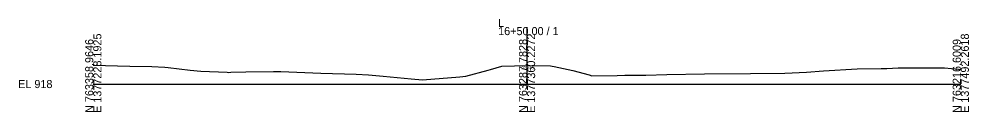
# Model space of a CAD drawing. Extents: x -26 to 303, y -10 to 6523.
# Drawn here: x -25.7 to 302.8, y 6490.3 to 6522.5 of the extents above; entities that cross this region are included whole.
import ezdxf

# ---------------------------------------------------------------- set-up
doc = ezdxf.new("R2010")
doc.units = 0
for name, color, linetype in [('Exist Cross Section Cell', 7, 'Continuous'), ('Exist XS Center Line Elevation Label', 7, 'Continuous'), ('Exist XS Ground Line', 7, 'Continuous')]:
    doc.layers.add(name, color=color, linetype=linetype)

msp = doc.modelspace()

# ---------------------------------------------------------------- linework, layer by layer
at = {"layer": 'Exist Cross Section Cell'}
for p, q in [((150, 6500), (150, 6519.73)), ((0, 6500), (150, 6500)), ((150, 6500), (300, 6500))]:
    msp.add_line(p, q, dxfattribs=at)
at = {"layer": 'Exist XS Ground Line'}
for p, q in [((0, 6506.58), (12.58, 6506.17)), ((12.58, 6506.17), (20.24, 6506.09)), ((20.24, 6506.09), (24.73, 6505.83)), ((24.73, 6505.83), (25.88, 6505.69)), ((25.88, 6505.69), (33.52, 6504.75)), ((136.51, 6504.81), (137.33, 6505)), ((137.33, 6505), (141.25, 6506.22)), ((141.25, 6506.22), (150.01, 6506.4)), ((150.01, 6506.4), (158.1, 6506.25)), ((158.1, 6506.25), (158.65, 6506.24)), ((158.65, 6506.24), (159.41, 6506.08)), ((159.41, 6506.08), (165.89, 6504.71)), ((254.47, 6504.72), (262.17, 6505.14)), ((262.17, 6505.14), (264.11, 6505.21)), ((264.11, 6505.21), (272.51, 6505.33)), ((272.51, 6505.33), (274.38, 6505.42)), ((274.38, 6505.42), (278.3, 6505.63)), ((278.3, 6505.63), (283.94, 6505.59)), ((283.94, 6505.59), (288.94, 6505.61)), ((288.94, 6505.61), (294.35, 6505.57)), ((294.35, 6505.57), (299.25, 6505.1)), ((299.25, 6505.1), (300, 6505.04)), ((33.52, 6504.75), (37.18, 6504.45)), ((37.18, 6504.45), (46.24, 6504.1)), ((46.24, 6504.1), (46.74, 6504.05)), ((46.74, 6504.05), (47.54, 6504.11)), ((47.54, 6504.11), (52.77, 6504.19)), ((52.77, 6504.19), (62.28, 6504.32)), ((62.28, 6504.32), (63.47, 6504.33)), ((63.47, 6504.33), (64.9, 6504.32)), ((64.9, 6504.32), (78.72, 6503.77)), ((78.72, 6503.77), (90.94, 6503.38)), ((90.94, 6503.38), (95.22, 6503.21)), ((95.22, 6503.21), (100.29, 6502.72)), ((100.29, 6502.72), (109.9, 6501.82)), ((109.9, 6501.82), (113.86, 6501.43)), ((113.86, 6501.43), (126.79, 6502.46)), ((126.79, 6502.46), (128.89, 6502.76)), ((128.89, 6502.76), (136.51, 6504.81)), ((165.89, 6504.71), (171.5, 6503.13)), ((171.5, 6503.13), (172.43, 6502.88)), ((172.43, 6502.88), (181.2, 6502.94)), ((181.2, 6502.94), (183.81, 6503.06)), ((183.81, 6503.06), (187.89, 6503.04)), ((187.89, 6503.04), (191.05, 6503.11)), ((191.05, 6503.11), (198.38, 6503.29)), ((198.38, 6503.29), (211.39, 6503.52)), ((211.39, 6503.52), (227.29, 6503.7)), ((227.29, 6503.7), (239.11, 6503.72)), ((239.11, 6503.72), (246.61, 6504.14)), ((246.61, 6504.14), (252.5, 6504.6)), ((252.5, 6504.6), (254.47, 6504.72))]:
    msp.add_line(p, q, dxfattribs=at)

# ---------------------------------------------------------------- texts
at = {"layer": 'Exist Cross Section Cell'}
for s, p in [('L', (140, 6519.73)), ('16+50.00 / 1', (140, 6516.93)), ('EL 918', (-26, 6498.6))]:
    msp.add_text(s, height=2.8, dxfattribs=at).set_placement(p)
for s, p in [('N 763358.9646', (0, 6490)), ('E 1377228.1925', (2.8, 6490)), ('N 763287.7828', (150, 6490)), ('E 1377360.2272', (152.8, 6490)), ('N 763216.6009', (300, 6490)), ('E 1377492.2618', (302.8, 6490))]:
    msp.add_text(s, height=2.8, rotation=90, dxfattribs=at).set_placement(p)
at = {"layer": 'Exist XS Center Line Elevation Label'}
msp.add_text('924.40', height=0.998, dxfattribs=at).set_placement((148.07, 6505.05))

doc.saveas('drawing.dxf')
